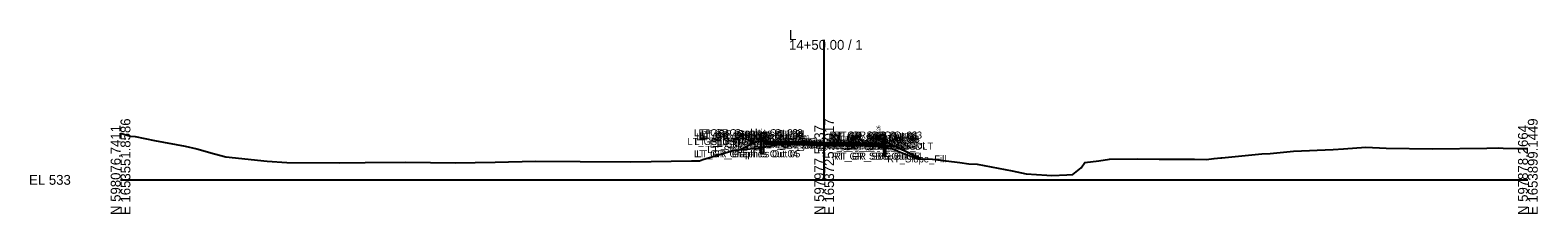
# Model space of a CAD drawing. Extents: x -26 to 403, y -10 to 6021.
# Drawn here: x -25.7 to 402.8, y 2990.3 to 3042.6 of the extents above; entities that cross this region are included whole.
import ezdxf

# ---------------------------------------------------------------- set-up
doc = ezdxf.new("R2010")
doc.units = 0
for name, color, linetype in [('Default', 7, 'Continuous'), ('Exist Cross Section Cell', 7, 'Continuous'), ('Exist XS Ground Line', 7, 'Continuous'), ('Prop CMT Conc Surface', 7, 'Continuous'), ('Prop CMT Concrete Structures', 7, 'Continuous'), ('Prop CMT Guardrail Graphics', 7, 'Continuous'), ('Prop CMT Guardrail SBG', 7, 'Continuous'), ('Prop CMT Pvmt Course 1', 7, 'Continuous'), ('Prop CMT Pvmt Course 2', 7, 'Continuous'), ('Prop CMT Pvmt Course 3', 7, 'Continuous'), ('Prop CMT Pvmt Course SBG', 7, 'Continuous'), ('Prop CMT Pvmt Surface', 7, 'Continuous'), ('Prop CMT Pvmt Surface Shoulder', 7, 'Continuous'), ('Prop CMT Shld Paved Course 1', 7, 'Continuous'), ('Prop CMT Shld Paved Course 2', 7, 'Continuous'), ('Prop CMT Shld Paved Course 3', 7, 'Continuous'), ('Prop CMT Slope Grass', 7, 'Continuous'), ('Prop CMT Subgrade Earthwork', 7, 'Continuous'), ('Prop XS Earthwork Shape', 7, 'Continuous'), ('Prop XS Hydro Elevations', 7, 'Continuous'), ('Prop XS SE Text', 7, 'Continuous'), ('Prop XS Side Slope Text', 7, 'Continuous')]:
    doc.layers.add(name, color=color, linetype=linetype)

msp = doc.modelspace()

# ---------------------------------------------------------------- linework, layer by layer
at = {"layer": 'Exist Cross Section Cell'}
for p, q in [((200, 3000), (200, 3039.84)), ((0, 3000), (200, 3000)), ((200, 3000), (400, 3000))]:
    msp.add_line(p, q, dxfattribs=at)
at = {"layer": 'Exist XS Ground Line'}
msp.add_lwpolyline([(0, 3013.28), (2.79, 3012.47), (4.11, 3012.3), (9.62, 3011.24), (18.35, 3009.63), (21.72, 3008.8), (26.69, 3007.45), (29.9, 3006.6), (41.7, 3005.34), (47.24, 3004.95), (62.13, 3004.82), (69.53, 3004.98), (81.1, 3005), (95.14, 3004.86), (106.44, 3005), (117.97, 3005.35), (130.61, 3005.25), (145.03, 3005.16), (162.25, 3005.44), (164.59, 3005.43), (165.46, 3005.78), (174.43, 3008.45), (177.22, 3008.69), (182.4, 3009.18), (186.67, 3009.98), (188.78, 3010.25), (198.85, 3010.41), (200, 3010.43), (200.49, 3010.44), (209.17, 3010.16), (211.81, 3010.09), (211.95, 3010.06), (214.2, 3009.67), (219.37, 3008.88), (221.37, 3008.01), (226.66, 3005.96), (230.77, 3005.93), (238.58, 3004.97), (241.07, 3004.52), (243.5, 3004.44), (253.4, 3002.58), (257.36, 3001.73), (263.31, 3001.33), (264.68, 3001.26), (268.97, 3001.39), (270.69, 3001.56), (272.99, 3003.46), (274.11, 3004.96), (278.09, 3005.43), (281.11, 3005.89), (289.18, 3005.95), (295.18, 3005.87), (298.55, 3005.87), (300.56, 3005.9), (301.61, 3005.92), (305.22, 3005.86), (308.54, 3005.82), (310.8, 3006.11), (312.76, 3006.29), (313.01, 3006.31), (324.42, 3007.38), (326.77, 3007.51), (333.43, 3008.17), (344.71, 3008.64), (347.63, 3008.83), (353.93, 3009.31), (359.72, 3009.01), (372.86, 3008.82), (388.36, 3009.06), (391.69, 3009.1), (392.99, 3009.07), (397.06, 3008.97), (400, 3008.92)], dxfattribs=at)
at = {"layer": 'Prop CMT Conc Surface'}
msp.add_lwpolyline([(213.58, 3010.35), (215.92, 3010.26), (216.58, 3010.6)], dxfattribs=at)
at = {"layer": 'Prop CMT Concrete Structures'}
for points in [[(213.58, 3010.35), (215.92, 3010.26), (216.58, 3010.6)], [(213.58, 3009.94), (213.58, 3010.35)], [(216.58, 3009.94), (213.58, 3009.94)], [(216.58, 3010.6), (216.58, 3009.94)]]:
    msp.add_lwpolyline(points, dxfattribs=at)
at = {"layer": 'Prop CMT Guardrail Graphics'}
for points in [[(182.07, 3007.43), (182.07, 3013.43)], [(182.07, 3013.43), (183.4, 3013.43), (183.67, 3013.14)], [(183.67, 3013.14), (183.4, 3012.85)], [(183.4, 3012.85), (183.67, 3012.56)], [(183.67, 3012.56), (183.4, 3012.27), (182.73, 3012.27)], [(182.73, 3012.27), (182.73, 3007.43)], [(182.73, 3007.43), (182.07, 3007.43)]]:
    msp.add_lwpolyline(points, dxfattribs=at)
at = {"layer": 'Prop CMT Guardrail SBG'}
for points in [[(217.52, 3012.76), (216.19, 3012.76), (215.92, 3012.47)], [(217.52, 3006.76), (217.52, 3012.76)], [(215.92, 3012.47), (216.19, 3012.18)], [(216.19, 3012.18), (215.92, 3011.89)], [(215.92, 3011.89), (216.19, 3011.59), (216.85, 3011.59)], [(216.85, 3011.59), (216.85, 3006.76)], [(216.85, 3006.76), (217.52, 3006.76)]]:
    msp.add_lwpolyline(points, dxfattribs=at)
at = {"layer": 'Prop CMT Pvmt Course 1'}
for points in [[(200, 3010.63), (188, 3010.87)], [(188, 3010.87), (188, 3010.66)], [(188, 3010.66), (200, 3010.42)], [(200, 3010.42), (200, 3010.63)], [(200, 3010.63), (212, 3010.39)], [(200, 3010.42), (200, 3010.63)], [(212, 3010.18), (200, 3010.42)], [(212, 3010.39), (212, 3010.18)]]:
    msp.add_lwpolyline(points, dxfattribs=at)
msp.add_lwpolyline([(200, 3010.42), (200, 3010.42), (200, 3010.42), (200, 3010.42)], close=True, dxfattribs=at)
msp.add_lwpolyline([(200, 3010.42), (200, 3010.42), (200, 3010.42), (200, 3010.42)], close=True, dxfattribs=at)
at = {"layer": 'Prop CMT Pvmt Course 2'}
for points in [[(200, 3010.42), (188, 3010.66)], [(188, 3010.66), (188, 3010.45)], [(188, 3010.45), (200, 3010.21)], [(200, 3010.21), (200, 3010.42)], [(200, 3010.21), (200, 3010.42)], [(200, 3010.42), (212, 3010.18)], [(212, 3009.97), (200, 3010.21)], [(212, 3010.18), (212, 3009.97)]]:
    msp.add_lwpolyline(points, dxfattribs=at)
at = {"layer": 'Prop CMT Pvmt Course 3'}
for points in [[(200, 3010.21), (188, 3010.45)], [(188, 3010.45), (188, 3010.12)], [(188, 3010.12), (200, 3009.88)], [(200, 3009.88), (200, 3010.21)], [(200, 3010.21), (212, 3009.97)], [(200, 3009.88), (200, 3010.21)], [(212, 3009.64), (200, 3009.88)], [(212, 3009.97), (212, 3009.64)]]:
    msp.add_lwpolyline(points, dxfattribs=at)
at = {"layer": 'Prop CMT Pvmt Course SBG'}
for points in [[(213.58, 3009.94), (216.58, 3009.94), (217.08, 3009.94), (217.42, 3009.6)], [(213.58, 3009.6), (213.58, 3009.94)], [(217.42, 3009.6), (213.58, 3009.6)]]:
    msp.add_lwpolyline(points, dxfattribs=at)
at = {"layer": 'Prop CMT Pvmt Surface'}
for points in [[(200, 3010.63), (188, 3010.87)], [(200, 3010.63), (212, 3010.39)]]:
    msp.add_lwpolyline(points, dxfattribs=at)
at = {"layer": 'Prop CMT Pvmt Surface Shoulder'}
for points in [[(188, 3010.87), (184, 3010.95)], [(212, 3010.39), (213.58, 3010.35)]]:
    msp.add_lwpolyline(points, dxfattribs=at)
at = {"layer": 'Prop CMT Shld Paved Course 1'}
for points in [[(188, 3010.87), (184, 3010.95), (183.8, 3010.74)], [(183.8, 3010.74), (188, 3010.66)], [(188, 3010.66), (188, 3010.87)], [(212, 3010.39), (213.58, 3010.35)], [(212, 3010.18), (212, 3010.39)], [(213.58, 3010.15), (212, 3010.18)], [(213.58, 3010.35), (213.58, 3010.15)]]:
    msp.add_lwpolyline(points, dxfattribs=at)
at = {"layer": 'Prop CMT Shld Paved Course 2'}
for points in [[(188, 3010.66), (183.8, 3010.74), (183.59, 3010.54)], [(183.59, 3010.54), (188, 3010.45)], [(188, 3010.45), (188, 3010.66)], [(212, 3010.18), (213.58, 3010.15)], [(212, 3009.97), (212, 3010.18)], [(213.58, 3009.94), (212, 3009.97)], [(213.58, 3010.15), (213.58, 3009.94)]]:
    msp.add_lwpolyline(points, dxfattribs=at)
at = {"layer": 'Prop CMT Shld Paved Course 3'}
for points in [[(188, 3010.45), (183.59, 3010.54), (183.59, 3010.54), (183.26, 3010.21)], [(183.26, 3010.21), (188, 3010.12)], [(188, 3010.12), (188, 3010.45)], [(212, 3009.97), (213.58, 3009.94)], [(212, 3009.64), (212, 3009.97)], [(213.58, 3009.6), (212, 3009.64)], [(213.58, 3009.94), (213.58, 3009.6)]]:
    msp.add_lwpolyline(points, dxfattribs=at)
at = {"layer": 'Prop CMT Slope Grass'}
for points in [[(180.67, 3010.81), (176.27, 3008.61)], [(183.67, 3010.93), (180.67, 3010.81)], [(184, 3010.95), (183.67, 3010.93)], [(216.58, 3010.6), (217.35, 3011), (227.44, 3005.96)]]:
    msp.add_lwpolyline(points, dxfattribs=at)
at = {"layer": 'Prop CMT Subgrade Earthwork'}
for points in [[(183.26, 3010.21), (182.59, 3010.89)], [(188, 3010.12), (183.26, 3010.21)], [(200, 3009.88), (188, 3010.12)], [(200, 3009.88), (212, 3009.64)], [(212, 3009.64), (213.58, 3009.6)], [(213.58, 3009.6), (213.58, 3009.6)], [(213.58, 3009.6), (217.42, 3009.6), (220.15, 3009.6)]]:
    msp.add_lwpolyline(points, dxfattribs=at)
at = {"layer": 'Prop XS Earthwork Shape'}
for points in [[(182.59, 3010.89), (180.67, 3010.81), (176.27, 3008.61), (177.22, 3008.69), (182.4, 3009.18), (186.67, 3009.98), (187.75, 3010.12), (183.26, 3010.21)], [(203.14, 3010.35), (209.17, 3010.16), (211.81, 3010.09), (211.95, 3010.06), (214.2, 3009.67), (214.62, 3009.6), (213.58, 3009.6), (212, 3009.64), (200, 3009.88), (188, 3010.12), (187.75, 3010.12), (188.78, 3010.25), (198.85, 3010.41), (199.57, 3010.43), (200, 3010.42)], [(199.57, 3010.43), (200, 3010.43), (200, 3010.42)], [(200, 3010.42), (200, 3010.43), (200.49, 3010.44), (203.14, 3010.35)], [(219.37, 3008.88), (221.37, 3008.01), (226.66, 3005.96), (227.44, 3005.96), (220.15, 3009.6), (217.42, 3009.6), (214.62, 3009.6)]]:
    msp.add_lwpolyline(points, close=True, dxfattribs=at)

# ---------------------------------------------------------------- texts
at = {"layer": 'Default'}
for s, height, p in [('LT_GR_Graphics Out 03', 2, (162.97, 3012.43)), ('LT_GR_Graphics Out 06', 2, (163.59, 3011.27)), ('LT_GR_Graphics Out 02', 2, (164.3, 3012.43)), ('LT_GR_Graphics Out 09', 2, (164.3, 3011.85)), ('LT_GR_Graphics Out 07', 2, (164.3, 3011.27)), ('LT_GR_Graphics Out 08', 2, (164.57, 3011.56)), ('LT_GR_Graphics Out 01', 2, (165.14, 3012.14)), ('RT_GR_SBG Out 08', 2, (201.22, 3010.89)), ('RT_GR_SBG Out 02', 2, (201.49, 3011.76)), ('RT_GR_SBG Out 09', 2, (201.49, 3011.18)), ('RT_GR_SBG Out 07', 2, (201.49, 3010.59)), ('RT_GR_SBG Out 01', 2, (201.79, 3011.47)), ('RT_GR_SBG Out 06', 2, (202.11, 3010.59)), ('RT_GR_SBG Out 03', 2, (202.83, 3011.76)), ('LT_GS_OS_GR_Face_Graphics', 2, (161.13, 3009.93)), ('LT_GR_Graphics Out 04', 2, (162.97, 3006.43)), ('LT_Sub_Trench_Out_DLT', 2, (163.15, 3009.89)), ('LT_GR_Graphics Out 05', 2, (163.63, 3006.43)), ('LT_Slope_Fill', 2, (166.79, 3007.61)), ('LT_Sub_Trench_Out', 2, (167.47, 3009.21)), ('LT_PS3_Shelf_Out', 2, (169.58, 3009.54)), ('LT_GS_OS_CTL', 2, (170.04, 3009.81)), ('LT_PS3_OEOP', 2, (173.83, 3009.54)), ('LT_PS2_OEOP', 2, (174.03, 3009.74)), ('LT_PS1_OEOP', 2, (174.8, 3009.95)), ('LT_Sub_OEOT', 2, (178.08, 3009.12)), ('LT_PV2_OEOT', 2, (178.17, 3009.66)), ('LT_PV3_OEOT', 2, (178.17, 3009.45)), ('LT_PV1_OEOT', 2, (178.74, 3009.87)), ('RT_Sub_OEEOP', 2, (189.17, 3008.88)), ('LT_Sub_OEEOP', 2, (189.21, 3008.88)), ('RT_PV2_OEEOP', 2, (189.26, 3009.42)), ('RT_PV3_OEEOP', 2, (189.26, 3009.21)), ('LT_PV2_OEEOP', 2, (189.31, 3009.42)), ('LT_PV3_OEEOP', 2, (189.31, 3009.21)), ('RT_PV1_OEEOP', 2, (189.83, 3009.42)), ('LT_PV1_OEEOP', 2, (189.87, 3009.42)), ('RT_PV2_IEEOP', 2, (189.91, 3009.42)), ('LT_PV2_IEEOP', 2, (189.95, 3009.42)), ('RT_PV1_IEEOP', 2, (190.47, 3009.42)), ('LT_PV1_IEEOP', 2, (190.52, 3009.42)), ('PV2_PGL', 2, (193.91, 3009.42)), ('PV1_PGL', 2, (194.47, 3009.63)), ('RT_Sub_OEOP_SBG', 2, (199.99, 3008.6)), ('RT_SBG_C1 Shelf Out', 2, (201.18, 3008.94)), ('RT_Sub_OEOT', 2, (202.03, 3008.64)), ('RT_PV2_OEOT', 2, (202.13, 3009.18)), ('RT_PV3_OEOT', 2, (202.13, 3008.97)), ('RT_PV1_OEOT', 2, (202.69, 3009.39)), ('RT_CG_Bot_IE', 2, (203.45, 3008.94)), ('RT_Sub_OEOP', 2, (203.65, 3008.6)), ('RT_PS2_OEOP', 2, (203.77, 3009.15)), ('RT_PS3_OEOP', 2, (203.77, 3008.94)), ('RT_CG_Top_Gut', 2, (204.11, 3009.26)), ('RT_PS1_OEOP', 2, (204.34, 3009.35)), ('RT_Sub_SBG Out', 2, (204.55, 3008.6)), ('RT_CG_Top_BOC', 2, (204.82, 3009.6)), ('RT_CG_Bot_BOC', 2, (204.85, 3008.94)), ('RT_GS_OS_CTL', 2, (206.68, 3010)), ('RT_Sub_OSS_DLT', 2, (207.5, 3008.6)), ('RT_GR_SBG Out 05', 2, (202.16, 3005.76)), ('RT_GR_SBG Out 04', 2, (202.83, 3005.76)), ('RT_Slope_Fill', 2, (217.91, 3004.96)), ('-', 0.0001, (0, 3000))]:
    msp.add_text(s, height=height, dxfattribs=at).set_placement(p)
at = {"layer": 'Exist Cross Section Cell'}
for s, p in [('L', (190, 3039.84)), ('14+50.00 / 1', (190, 3037.04)), ('EL 533', (-26, 2998.6))]:
    msp.add_text(s, height=2.8, dxfattribs=at).set_placement(p)
for s, p in [('E 1653551.8586', (2.8, 2990)), ('E 1653725.5017', (202.8, 2990)), ('E 1653899.1449', (402.8, 2990)), ('N 598076.7411', (0, 2990)), ('N 597977.5037', (200, 2990)), ('N 597878.2664', (400, 2990))]:
    msp.add_text(s, height=2.8, rotation=90, dxfattribs=at).set_placement(p)
at = {"layer": 'Prop XS Hydro Elevations'}
msp.add_text('543.26', height=1, rotation=90, dxfattribs=at).set_placement((215.92, 3011.26))
at = {"layer": 'Prop XS SE Text'}
for p in [(192.27, 3011.78), (204.27, 3011.54)]:
    msp.add_text('0.020', height=1, rotation=358.8542, dxfattribs=at).set_placement(p)
at = {"layer": 'Prop XS Side Slope Text'}
for rotation, p in [(26.5651, (177.43, 3010.03)), (333.4349, (222.02, 3009.5))]:
    msp.add_text('2:1', height=1, rotation=rotation, dxfattribs=at).set_placement(p)

doc.saveas('drawing.dxf')
